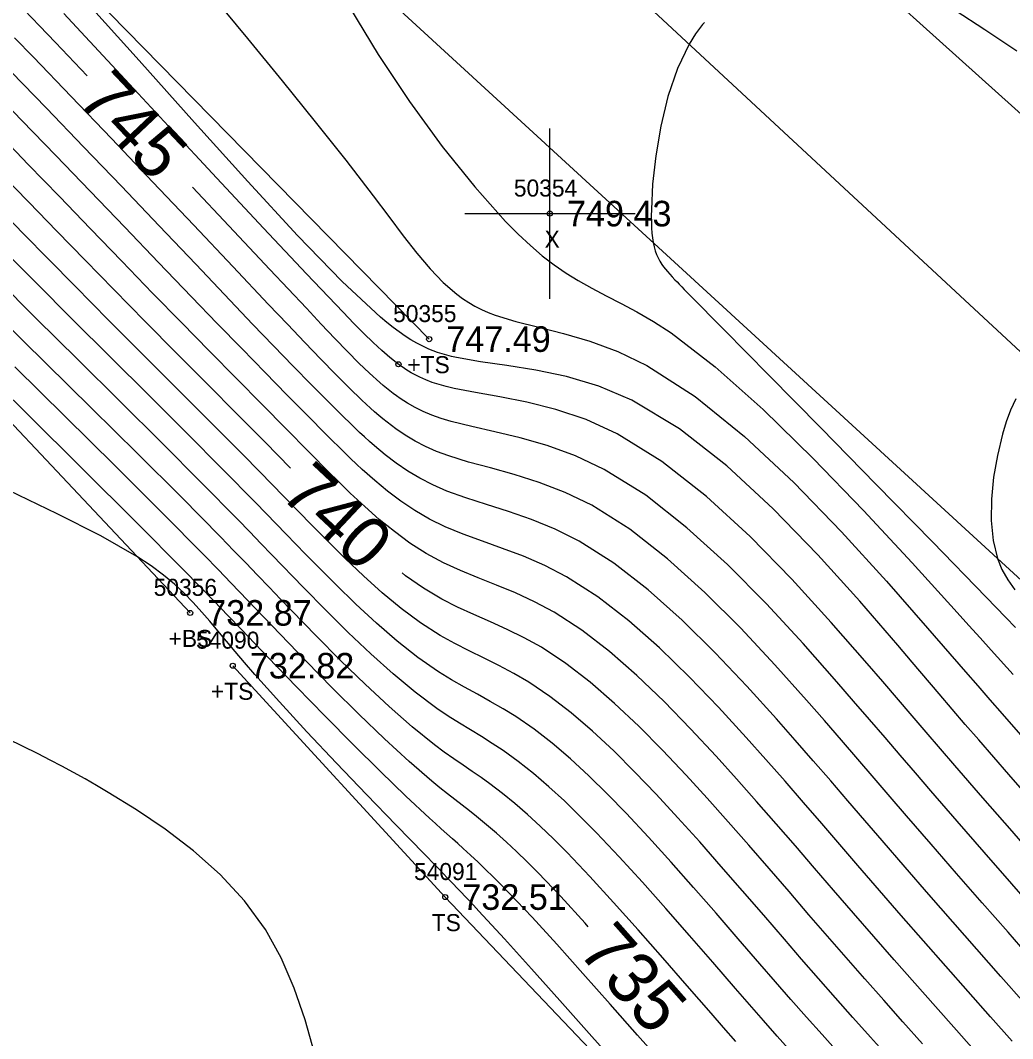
# Model space of a CAD drawing. Extents: x 1378535 to 1380697, y 997729 to 1000024.
# Drawn here: x 1379536.7 to 1379595, y 999000.3 to 999060.1 of the extents above; entities that cross this region are included whole.
import ezdxf

# ---------------------------------------------------------------- set-up
doc = ezdxf.new("R2010")
doc.units = 0
for name, color, linetype in [('RD_DTM_BkLn1', 7, 'Continuous'), ('RD_DTM_BkLn2', 7, 'Continuous'), ('RD_DTM_BkLn_txCode', 7, 'Continuous'), ('RD_DTM_Major1', 7, 'Continuous'), ('RD_DTM_Major1_Lbl', 7, 'Continuous'), ('RD_DTM_Minor1', 7, 'Continuous'), ('RD_EX_Misc', 7, 'Continuous'), ('RD_EX_Misc_txCode', 7, 'Continuous'), ('RD_EX_Road', 7, 'Continuous'), ('RD_EX_TX_Misc_ELEV', 7, 'Continuous'), ('RD_SMD_Locator', 7, 'Continuous')]:
    doc.layers.add(name, color=color, linetype=linetype)

msp = doc.modelspace()

# ---------------------------------------------------------------- linework, layer by layer
at = {"layer": 'RD_DTM_BkLn1'}
msp.add_lwpolyline([(1379644.889, 998995.516), (1379603.59, 999033.022), (1379560.539, 999073.024), (1379518.05, 999111.381), (1379475.069, 999150.602), (1379431.045, 999190.013), (1379385.062, 999231.968), (1379339.18, 999273.058), (1379294.588, 999314.047), (1379247.38, 999356.59), (1379201.7, 999398.205), (1379156.533, 999438.891)], dxfattribs=at)
at = {"layer": 'RD_DTM_BkLn2'}
for points in [[(1379560.71, 999041.369), (1379522.229, 999080.615), (1379488.974, 999108.847), (1379453.566, 999142.959)], [(1379546.679, 999025.297), (1379508.429, 999065.934), (1379476.253, 999096.185), (1379454.22, 999110.396), (1379428.749, 999089.976)], [(1379549.178, 999022.196), (1379561.654, 999008.614), (1379573.991, 998995.636), (1379587.739, 998979.101), (1379600.39, 998963.869), (1379618.836, 998956.235), (1379632.894, 998950.83), (1379660.439, 998956.621)]]:
    msp.add_lwpolyline(points, dxfattribs=at)
at = {"layer": 'RD_DTM_Major1'}
for points in [[(1379595.196, 999058.28), (1379593.322, 999059.53), (1379591.577, 999060.653), (1379590.026, 999061.63), (1379589.781, 999061.783), (1379589.544, 999061.931), (1379589.314, 999062.074), (1379589.09, 999062.212), (1379588.871, 999062.345), (1379588.658, 999062.473), (1379588.101, 999062.793), (1379587.565, 999063.071), (1379587.035, 999063.303), (1379586.498, 999063.483), (1379585.94, 999063.607), (1379585.346, 999063.67), (1379584.833, 999063.655)], [(1379552.566, 999033.796), (1379551.072, 999035.312), (1379549.431, 999036.967), (1379547.69, 999038.719), (1379545.882, 999040.541), (1379544.037, 999042.406), (1379542.188, 999044.285), (1379540.511, 999046.002), (1379538.852, 999047.709), (1379537.206, 999049.406), (1379535.566, 999051.093), (1379533.928, 999052.77), (1379532.286, 999054.438), (1379530.585, 999056.15), (1379528.884, 999057.849), (1379527.193, 999059.531), (1379525.522, 999061.194)], [(1379540.63, 999056.823), (1379538.777, 999058.772), (1379537.839, 999059.753), (1379536.943, 999060.69)], [(1379576.863, 999059.951), (1379576.761, 999059.84), (1379576.346, 999059.295), (1379575.964, 999058.691), (1379575.277, 999057.247), (1379574.727, 999055.611), (1379574.307, 999053.876), (1379574.009, 999052.132), (1379573.826, 999050.471), (1379573.75, 999048.983), (1379573.746, 999048.603), (1379573.751, 999048.246), (1379573.765, 999047.91), (1379573.787, 999047.598), (1379573.818, 999047.309), (1379573.858, 999047.043), (1379573.91, 999046.79), (1379573.974, 999046.558), (1379574.051, 999046.344), (1379574.142, 999046.142), (1379574.249, 999045.947), (1379574.372, 999045.755), (1379574.473, 999045.617), (1379574.583, 999045.475), (1379574.704, 999045.33), (1379574.836, 999045.179), (1379574.979, 999045.021), (1379575.134, 999044.854), (1379575.259, 999044.723), (1379575.392, 999044.585), (1379575.531, 999044.442), (1379575.678, 999044.291), (1379575.832, 999044.134), (1379575.994, 999043.97), (1379578.027, 999041.908), (1379580.656, 999039.245), (1379583.694, 999036.162), (1379586.956, 999032.842), (1379590.254, 999029.468), (1379593.403, 999026.219), (1379594.558, 999025.018), (1379595.121, 999024.43)], [(1379596.532, 999007.539), (1379594.914, 999009.391), (1379593.293, 999011.244), (1379591.697, 999013.073), (1379590.152, 999014.854), (1379589.248, 999015.904), (1379588.358, 999016.941), (1379587.468, 999017.979), (1379586.562, 999019.034), (1379585.625, 999020.118), (1379584.644, 999021.248), (1379582.657, 999023.494), (1379580.501, 999025.829), (1379578.216, 999028.137), (1379575.842, 999030.3), (1379573.419, 999032.201), (1379570.988, 999033.724), (1379569.293, 999034.522), (1379567.641, 999035.122), (1379566.058, 999035.575), (1379564.571, 999035.928), (1379563.207, 999036.231), (1379561.993, 999036.533), (1379561.404, 999036.713), (1379560.86, 999036.909), (1379560.354, 999037.123), (1379559.88, 999037.357), (1379559.43, 999037.612), (1379558.998, 999037.891), (1379558.799, 999038.03), (1379558.601, 999038.176), (1379558.404, 999038.327), (1379558.206, 999038.486), (1379558.007, 999038.652), (1379557.805, 999038.825), (1379557.214, 999039.361), (1379556.586, 999039.966), (1379555.91, 999040.646), (1379555.177, 999041.404), (1379554.377, 999042.246), (1379553.5, 999043.177), (1379551.362, 999045.449), (1379548.943, 999048.019), (1379546.812, 999050.282)], [(1379570.048, 999006.875), (1379569.857, 999007.088), (1379568.433, 999008.64), (1379567.101, 999010.037), (1379566.458, 999010.683), (1379565.842, 999011.281), (1379565.244, 999011.84), (1379564.658, 999012.365), (1379564.078, 999012.863), (1379563.496, 999013.341), (1379563.081, 999013.671), (1379561.791, 999014.677), (1379561.339, 999015.036), (1379560.873, 999015.417), (1379559.528, 999016.579), (1379558.089, 999017.902), (1379556.585, 999019.348), (1379555.042, 999020.879), (1379553.489, 999022.457), (1379551.953, 999024.045), (1379550.532, 999025.529), (1379549.077, 999027.049), (1379548.313, 999027.841), (1379547.513, 999028.665), (1379545.017, 999031.196), (1379542.26, 999033.948), (1379539.347, 999036.827), (1379536.383, 999039.738)], [(1379589.669, 999000.004), (1379588.519, 999001.289), (1379587.392, 999002.556), (1379586.283, 999003.813), (1379585.186, 999005.065), (1379584.095, 999006.318), (1379583.004, 999007.578), (1379581.837, 999008.932), (1379580.66, 999010.296), (1379579.47, 999011.667), (1379578.263, 999013.04), (1379577.035, 999014.411), (1379575.785, 999015.777), (1379574.411, 999017.231), (1379573.013, 999018.643), (1379571.596, 999019.984), (1379570.167, 999021.223), (1379568.732, 999022.331), (1379567.298, 999023.276), (1379566.29, 999023.836), (1379565.29, 999024.326), (1379564.302, 999024.772), (1379563.331, 999025.201), (1379562.38, 999025.638), (1379561.455, 999026.11), (1379560.37, 999026.757), (1379559.321, 999027.482), (1379559.119, 999027.64)]]:
    msp.add_lwpolyline(points, dxfattribs=at)
at = {"layer": 'RD_DTM_Minor1'}
for points in [[(1379598.415, 999011.597), (1379594.73, 999015.806), (1379592.965, 999017.837), (1379592.181, 999018.747), (1379591.41, 999019.648), (1379590.639, 999020.552), (1379589.053, 999022.413), (1379588.215, 999023.395), (1379585.981, 999025.98), (1379583.528, 999028.703), (1379580.91, 999031.405), (1379578.181, 999033.927), (1379575.394, 999036.109), (1379572.604, 999037.791), (1379570.665, 999038.611), (1379568.779, 999039.175), (1379566.972, 999039.553), (1379565.274, 999039.816), (1379563.712, 999040.035), (1379562.313, 999040.282), (1379562.024, 999040.348), (1379561.743, 999040.421), (1379561.471, 999040.499), (1379561.204, 999040.586), (1379560.943, 999040.68), (1379560.686, 999040.783), (1379560.567, 999040.835), (1379560.448, 999040.889), (1379560.329, 999040.946), (1379560.211, 999041.005), (1379560.093, 999041.066), (1379559.975, 999041.13), (1379559.639, 999041.326), (1379559.299, 999041.545), (1379558.953, 999041.787), (1379558.598, 999042.053), (1379558.23, 999042.346), (1379557.848, 999042.666), (1379555.602, 999044.755), (1379552.975, 999047.456), (1379550.056, 999050.618), (1379546.93, 999054.089), (1379543.687, 999057.72), (1379540.413, 999061.36)], [(1379547.953, 999061.567), (1379550.052, 999059.015), (1379552.087, 999056.522), (1379554.018, 999054.127), (1379555.807, 999051.868), (1379557.415, 999049.784), (1379558.333, 999048.563), (1379559.183, 999047.437), (1379559.986, 999046.41), (1379560.763, 999045.492), (1379561.535, 999044.687), (1379562.323, 999044.004), (1379562.67, 999043.751), (1379563.027, 999043.519), (1379563.394, 999043.307), (1379563.776, 999043.114), (1379564.174, 999042.938), (1379564.591, 999042.776), (1379565.798, 999042.403), (1379567.137, 999042.063), (1379568.592, 999041.696), (1379570.147, 999041.241), (1379571.785, 999040.639), (1379573.489, 999039.828), (1379576.329, 999038.004), (1379579.226, 999035.654), (1379582.11, 999032.949), (1379584.908, 999030.057), (1379587.551, 999027.15), (1379589.966, 999024.398), (1379592.194, 999021.83), (1379592.907, 999021.009), (1379593.618, 999020.191), (1379594.338, 999019.367), (1379596.25, 999017.191)], [(1379556.031, 999060.851), (1379557.715, 999058.071), (1379559.558, 999055.311), (1379561.474, 999052.684), (1379563.38, 999050.3), (1379565.188, 999048.273), (1379565.931, 999047.524), (1379566.648, 999046.855), (1379567.349, 999046.257), (1379568.044, 999045.722), (1379568.742, 999045.239), (1379569.453, 999044.8), (1379570.261, 999044.352), (1379571.103, 999043.917), (1379571.982, 999043.467), (1379572.905, 999042.974), (1379573.879, 999042.408), (1379574.908, 999041.742), (1379577.504, 999039.747), (1379580.322, 999037.231), (1379583.258, 999034.362), (1379586.205, 999031.308), (1379589.057, 999028.237), (1379591.71, 999025.319), (1379592.392, 999024.563), (1379593.056, 999023.826), (1379593.708, 999023.102), (1379594.993, 999021.673)], [(1379596.66, 999010.496), (1379594.925, 999012.479), (1379593.215, 999014.435), (1379591.566, 999016.334), (1379590.72, 999017.317), (1379589.888, 999018.288), (1379589.056, 999019.26), (1379587.337, 999021.266), (1379586.423, 999022.326), (1379584.314, 999024.738), (1379582.006, 999027.268), (1379579.548, 999029.778), (1379576.986, 999032.131), (1379574.369, 999034.189), (1379571.744, 999035.814), (1379569.916, 999036.643), (1379568.139, 999037.244), (1379566.444, 999037.671), (1379564.863, 999037.981), (1379563.427, 999038.229), (1379562.167, 999038.471), (1379561.713, 999038.579), (1379561.29, 999038.697), (1379560.891, 999038.827), (1379560.515, 999038.971), (1379560.155, 999039.131), (1379559.808, 999039.308), (1379559.649, 999039.399), (1379559.49, 999039.494), (1379559.333, 999039.594), (1379559.175, 999039.699), (1379559.018, 999039.81), (1379558.859, 999039.926), (1379558.402, 999040.289), (1379557.924, 999040.703), (1379557.419, 999041.172), (1379556.877, 999041.701), (1379556.29, 999042.292), (1379555.651, 999042.95), (1379553.502, 999045.203), (1379550.985, 999047.879), (1379548.239, 999050.822), (1379545.401, 999053.875), (1379542.61, 999056.882), (1379540.002, 999059.687), (1379539.267, 999060.475)], [(1379596.189, 999004.84), (1379594.69, 999006.552), (1379593.177, 999008.281), (1379591.666, 999010.008), (1379590.178, 999011.715), (1379588.731, 999013.386), (1379587.771, 999014.5), (1379586.825, 999015.602), (1379585.876, 999016.706), (1379584.911, 999017.825), (1379583.913, 999018.973), (1379582.867, 999020.164), (1379581.001, 999022.25), (1379578.996, 999024.394), (1379576.885, 999026.5), (1379574.702, 999028.471), (1379572.479, 999030.208), (1379570.251, 999031.616), (1379568.694, 999032.371), (1379567.173, 999032.958), (1379565.707, 999033.422), (1379564.317, 999033.806), (1379563.026, 999034.155), (1379561.855, 999034.514), (1379561.145, 999034.78), (1379560.489, 999035.07), (1379559.879, 999035.386), (1379559.305, 999035.728), (1379558.76, 999036.097), (1379558.233, 999036.493), (1379557.99, 999036.689), (1379557.747, 999036.891), (1379557.504, 999037.101), (1379557.26, 999037.319), (1379557.012, 999037.546), (1379556.759, 999037.781), (1379556.012, 999038.502), (1379555.208, 999039.304), (1379554.342, 999040.192), (1379553.405, 999041.169), (1379552.388, 999042.238), (1379551.285, 999043.405), (1379549.185, 999045.626), (1379546.89, 999048.051), (1379544.486, 999050.585), (1379542.059, 999053.136), (1379539.695, 999055.609), (1379537.48, 999057.911), (1379536.373, 999059.054)], [(1379595.655, 999002.377), (1379594.263, 999003.96), (1379592.856, 999005.56), (1379591.446, 999007.167), (1379590.044, 999008.771), (1379588.659, 999010.361), (1379587.304, 999011.926), (1379586.292, 999013.102), (1379585.289, 999014.269), (1379584.281, 999015.438), (1379583.255, 999016.622), (1379582.197, 999017.83), (1379581.093, 999019.076), (1379579.346, 999021.004), (1379577.491, 999022.961), (1379575.555, 999024.869), (1379573.563, 999026.649), (1379571.541, 999028.223), (1379569.516, 999029.513), (1379568.099, 999030.22), (1379566.71, 999030.787), (1379565.363, 999031.253), (1379564.075, 999031.659), (1379562.862, 999032.044), (1379561.74, 999032.447), (1379560.921, 999032.805), (1379560.16, 999033.198), (1379559.446, 999033.626), (1379558.771, 999034.087), (1379558.125, 999034.58), (1379557.497, 999035.103), (1379557.206, 999035.359), (1379556.915, 999035.623), (1379556.622, 999035.895), (1379556.325, 999036.175), (1379556.024, 999036.465), (1379555.715, 999036.766), (1379554.793, 999037.68), (1379553.797, 999038.686), (1379552.726, 999039.784), (1379551.577, 999040.974), (1379550.347, 999042.256), (1379549.034, 999043.631), (1379547.003, 999045.76), (1379544.853, 999048.017), (1379542.638, 999050.338), (1379540.415, 999052.66), (1379538.242, 999054.919), (1379536.175, 999057.052)], [(1379594.924, 999000.162), (1379593.658, 999001.589), (1379592.343, 999003.074), (1379591.029, 999004.562), (1379589.721, 999006.05), (1379588.424, 999007.534), (1379587.14, 999009.009), (1379585.874, 999010.472), (1379584.809, 999011.708), (1379583.749, 999012.94), (1379582.682, 999014.176), (1379581.596, 999015.423), (1379580.479, 999016.69), (1379579.321, 999017.983), (1379577.694, 999019.754), (1379575.99, 999021.527), (1379574.228, 999023.24), (1379572.426, 999024.834), (1379570.604, 999026.247), (1379568.779, 999027.419), (1379567.502, 999028.078), (1379566.244, 999028.621), (1379565.017, 999029.085), (1379563.833, 999029.504), (1379562.704, 999029.915), (1379561.64, 999030.352), (1379560.722, 999030.804), (1379559.86, 999031.305), (1379559.045, 999031.851), (1379558.266, 999032.437), (1379557.515, 999033.061), (1379556.78, 999033.716), (1379556.438, 999034.035), (1379556.095, 999034.362), (1379555.749, 999034.697), (1379555.398, 999035.042), (1379555.039, 999035.398), (1379554.67, 999035.766), (1379553.561, 999036.881), (1379552.36, 999038.097), (1379551.073, 999039.409), (1379549.707, 999040.81), (1379548.267, 999042.294), (1379546.76, 999043.854), (1379544.828, 999045.863), (1379542.835, 999047.941), (1379540.812, 999050.05), (1379538.79, 999052.152), (1379536.8, 999054.209), (1379534.874, 999056.185)], [(1379592.999, 998999.304), (1379591.663, 999000.798), (1379590.428, 999002.183), (1379589.208, 999003.561), (1379588.001, 999004.932), (1379586.805, 999006.299), (1379585.619, 999007.662), (1379584.44, 999009.023), (1379583.325, 999010.318), (1379582.207, 999011.616), (1379581.078, 999012.919), (1379579.932, 999014.229), (1379578.758, 999015.55), (1379577.551, 999016.884), (1379576.048, 999018.497), (1379574.496, 999020.088), (1379572.908, 999021.612), (1379571.294, 999023.025), (1379569.667, 999024.283), (1379568.04, 999025.34), (1379566.899, 999025.948), (1379565.771, 999026.466), (1379564.664, 999026.923), (1379563.586, 999027.35), (1379562.544, 999027.778), (1379561.546, 999028.237), (1379560.54, 999028.786), (1379559.582, 999029.398), (1379558.666, 999030.066), (1379557.782, 999030.782), (1379556.922, 999031.539), (1379556.076, 999032.33), (1379555.681, 999032.713), (1379555.285, 999033.103), (1379554.884, 999033.502), (1379554.475, 999033.913), (1379554.057, 999034.335), (1379553.625, 999034.772), (1379552.319, 999036.094), (1379550.902, 999037.527), (1379549.392, 999039.057), (1379547.805, 999040.668), (1379546.161, 999042.345), (1379544.476, 999044.073), (1379542.664, 999045.943), (1379540.836, 999047.836), (1379539.003, 999049.736), (1379537.176, 999051.626), (1379535.364, 999053.49)], [(1379587.675, 998999.21), (1379586.613, 999000.39), (1379585.581, 999001.548), (1379584.568, 999002.693), (1379583.567, 999003.833), (1379582.569, 999004.978), (1379581.565, 999006.136), (1379580.346, 999007.548), (1379579.108, 999008.98), (1379577.855, 999010.419), (1379576.588, 999011.854), (1379575.31, 999013.272), (1379574.024, 999014.661), (1379572.785, 999015.953), (1379571.541, 999017.19), (1379570.295, 999018.354), (1379569.047, 999019.428), (1379567.799, 999020.393), (1379566.552, 999021.232), (1379565.673, 999021.743), (1379564.798, 999022.204), (1379563.927, 999022.637), (1379563.063, 999023.061), (1379562.208, 999023.5), (1379561.362, 999023.975), (1379560.207, 999024.72), (1379559.072, 999025.56), (1379557.956, 999026.479), (1379556.856, 999027.463), (1379555.768, 999028.495), (1379554.692, 999029.561), (1379554.188, 999030.07), (1379553.682, 999030.587), (1379553.168, 999031.114), (1379552.102, 999032.21), (1379551.541, 999032.785), (1379549.823, 999034.529), (1379547.953, 999036.411), (1379545.978, 999038.389), (1379543.945, 999040.422), (1379541.904, 999042.469), (1379539.901, 999044.489), (1379538.373, 999046.042), (1379536.883, 999047.564), (1379535.416, 999049.066)], [(1379584.71, 998999.489), (1379583.772, 999000.538), (1379582.854, 999001.573), (1379581.947, 999002.604), (1379581.04, 999003.641), (1379580.124, 999004.695), (1379578.851, 999006.167), (1379577.551, 999007.668), (1379576.233, 999009.176), (1379574.908, 999010.67), (1379573.585, 999012.129), (1379572.272, 999013.531), (1379571.173, 999014.661), (1379570.085, 999015.728), (1379569.007, 999016.724), (1379567.936, 999017.641), (1379566.868, 999018.472), (1379565.801, 999019.21), (1379565.047, 999019.674), (1379564.293, 999020.105), (1379563.537, 999020.519), (1379562.781, 999020.935), (1379562.023, 999021.367), (1379561.263, 999021.835), (1379560.048, 999022.68), (1379558.831, 999023.637), (1379557.616, 999024.685), (1379556.405, 999025.804), (1379555.201, 999026.975), (1379554.007, 999028.177), (1379553.449, 999028.749), (1379552.887, 999029.327), (1379552.318, 999029.916), (1379551.735, 999030.519), (1379551.133, 999031.14), (1379550.506, 999031.784), (1379548.579, 999033.74), (1379546.477, 999035.849), (1379544.264, 999038.055), (1379542.006, 999040.301), (1379539.77, 999042.529), (1379537.619, 999044.683), (1379536.249, 999046.064)], [(1379581.965, 998999.527), (1379581.141, 999000.453), (1379580.326, 999001.375), (1379579.511, 999002.304), (1379578.685, 999003.251), (1379577.353, 999004.786), (1379575.987, 999006.357), (1379574.605, 999007.934), (1379573.224, 999009.485), (1379571.86, 999010.98), (1379570.531, 999012.386), (1379569.578, 999013.353), (1379568.648, 999014.255), (1379567.735, 999015.092), (1379566.834, 999015.864), (1379565.938, 999016.572), (1379565.044, 999017.216), (1379564.41, 999017.634), (1379563.772, 999018.033), (1379563.129, 999018.425), (1379562.479, 999018.824), (1379561.821, 999019.243), (1379561.154, 999019.693), (1379559.888, 999020.639), (1379558.593, 999021.714), (1379557.28, 999022.893), (1379555.958, 999024.149), (1379554.636, 999025.459), (1379553.324, 999026.795), (1379552.712, 999027.427), (1379552.097, 999028.065), (1379551.473, 999028.713), (1379550.833, 999029.377), (1379550.172, 999030.061), (1379549.481, 999030.771), (1379547.349, 999032.935), (1379545.015, 999035.271), (1379542.564, 999037.705), (1379540.079, 999040.165), (1379537.644, 999042.576), (1379535.342, 999044.866)], [(1379578.708, 999000.143), (1379577.987, 999000.961), (1379577.256, 999001.793), (1379575.856, 999003.398), (1379574.42, 999005.044), (1379572.972, 999006.69), (1379571.537, 999008.295), (1379570.141, 999009.82), (1379568.806, 999011.222), (1379568.006, 999012.027), (1379567.233, 999012.772), (1379566.481, 999013.462), (1379565.742, 999014.103), (1379565.01, 999014.7), (1379564.277, 999015.257), (1379563.757, 999015.63), (1379563.23, 999015.995), (1379562.696, 999016.361), (1379562.152, 999016.736), (1379561.596, 999017.13), (1379561.027, 999017.552), (1379559.719, 999018.602), (1379558.352, 999019.798), (1379556.942, 999021.109), (1379555.509, 999022.503), (1379554.069, 999023.95), (1379552.64, 999025.417), (1379551.976, 999026.107), (1379551.309, 999026.801), (1379550.634, 999027.505), (1379549.941, 999028.226), (1379549.223, 999028.969), (1379548.472, 999029.741), (1379546.141, 999032.104), (1379543.581, 999034.661), (1379540.893, 999037.324), (1379535.531, 999042.607)], [(1379574.553, 998998.696), (1379572.946, 999000.503), (1379571.331, 999002.329), (1379569.738, 999004.126), (1379568.199, 999005.843), (1379566.746, 999007.434), (1379565.411, 999008.847), (1379564.931, 999009.338), (1379564.47, 999009.8), (1379564.02, 999010.239), (1379563.579, 999010.661), (1379563.141, 999011.07), (1379562.702, 999011.472), (1379562.388, 999011.754), (1379562.07, 999012.039), (1379561.746, 999012.328), (1379561.414, 999012.624), (1379561.073, 999012.931), (1379560.722, 999013.25), (1379559.345, 999014.538), (1379557.842, 999015.992), (1379556.247, 999017.574), (1379554.594, 999019.244), (1379552.915, 999020.963), (1379551.243, 999022.693), (1379550.467, 999023.502), (1379549.688, 999024.314), (1379548.896, 999025.139), (1379548.079, 999025.986), (1379547.227, 999026.864), (1379546.327, 999027.785), (1379543.496, 999030.639), (1379540.366, 999033.753), (1379537.105, 999036.976), (1379533.881, 999040.161)], [(1379595.145, 999037.867), (1379594.836, 999037.207), (1379594.578, 999036.511), (1379594.358, 999035.78), (1379594.061, 999034.543), (1379593.844, 999033.261), (1379593.721, 999031.976), (1379593.707, 999030.727), (1379593.817, 999029.553), (1379594.066, 999028.495), (1379594.33, 999027.836), (1379594.67, 999027.229), (1379595.085, 999026.653)], [(1379571.888, 998998.614), (1379570.104, 999000.609), (1379568.376, 999002.548), (1379566.716, 999004.407), (1379565.131, 999006.163), (1379563.631, 999007.795), (1379563.318, 999008.13), (1379563.008, 999008.459), (1379562.393, 999009.107), (1379562.084, 999009.429), (1379561.773, 999009.752), (1379561.552, 999009.981), (1379561.328, 999010.212), (1379560.873, 999010.68), (1379560.641, 999010.918), (1379560.406, 999011.16), (1379558.768, 999012.842), (1379557.031, 999014.637), (1379555.263, 999016.482), (1379553.534, 999018.313), (1379551.914, 999020.069), (1379550.471, 999021.686), (1379549.871, 999022.383), (1379549.316, 999023.04), (1379548.305, 999024.249), (1379547.83, 999024.81), (1379547.363, 999025.348), (1379546.858, 999025.907), (1379546.329, 999026.451), (1379545.756, 999026.987), (1379545.117, 999027.521), (1379544.39, 999028.062), (1379543.554, 999028.617), (1379541.431, 999029.827), (1379538.879, 999031.117), (1379536.031, 999032.478)], [(1379553.984, 998999.458), (1379553.42, 999001.399), (1379552.78, 999003.266), (1379552.022, 999005.041), (1379551.101, 999006.705), (1379549.866, 999008.394), (1379548.437, 999009.933), (1379546.868, 999011.331), (1379545.214, 999012.596), (1379543.529, 999013.737), (1379541.867, 999014.763), (1379541.183, 999015.165), (1379540.507, 999015.551), (1379539.832, 999015.926), (1379539.152, 999016.294), (1379538.46, 999016.657), (1379537.752, 999017.021), (1379535.964, 999017.909)]]:
    msp.add_lwpolyline(points, dxfattribs=at)
at = {"layer": 'RD_EX_Misc'}
for p, q in [((1379567.797, 999043.737), (1379567.797, 999053.737)), ((1379562.797, 999048.737), (1379572.797, 999048.737))]:
    msp.add_line(p, q, dxfattribs=at)
at = {"layer": 'RD_EX_Road'}
for points in [[(1379652.216, 999003.544), (1379610.671, 999040.913), (1379567.405, 999079.792), (1379524.774, 999119.811), (1379481.793, 999158.312), (1379438.693, 999197.69), (1379392.81, 999238.626), (1379346.749, 999280.784), (1379301.799, 999321.656), (1379254.546, 999364.519), (1379209.475, 999405.54), (1379163.997, 999446.485)], [(1379637.067, 998987.215), (1379597.137, 999025.676), (1379553.307, 999065.907), (1379510.702, 999104.297), (1379468.488, 999142.894), (1379424.884, 999182.89), (1379377.902, 999224.837), (1379333.605, 999264.984), (1379287.277, 999307.211), (1379240.784, 999348.984), (1379194.921, 999391.17), (1379151.382, 999431.093)]]:
    msp.add_lwpolyline(points, dxfattribs=at)
at = {"layer": 'RD_SMD_Locator'}
for centre in [(1379567.797, 999048.737), (1379560.71, 999041.369), (1379558.905, 999039.89), (1379546.679, 999025.297), (1379549.178, 999022.196), (1379561.654, 999008.614)]:
    msp.add_circle(centre, 0.15, dxfattribs=at)

# ---------------------------------------------------------------- texts
at = {"layer": 'RD_DTM_BkLn_txCode'}
for s, p in [('50355', (1379558.592, 999042.369)), ('+TS', (1379559.427, 999039.369)), ('50356', (1379544.537, 999026.297)), ('+BS', (1379545.411, 999023.297)), ('54090', (1379547.021, 999023.196)), ('+TS', (1379547.895, 999020.196)), ('54091', (1379559.819, 999009.614)), ('TS', (1379560.859, 999006.614))]:
    msp.add_text(s, height=1, dxfattribs=at).set_placement(p)
at = {"layer": 'RD_DTM_Major1_Lbl'}
for s, rotation, p in [('745', 313.38533, (1379539.957, 999055.358)), ('740', 316.78788, (1379551.868, 999032.178)), ('735', 311.45734, (1379569.363, 999005.402))]:
    msp.add_text(s, height=3, rotation=rotation, dxfattribs=at).set_placement(p)
at = {"layer": 'RD_EX_Misc_txCode'}
for s, p in [('50354', (1379565.679, 999049.737)), ('X', (1379567.482, 999046.737))]:
    msp.add_text(s, height=1, dxfattribs=at).set_placement(p)
at = {"layer": 'RD_EX_TX_Misc_ELEV'}
for s, p in [('749.43', (1379568.797, 999047.987)), ('747.49', (1379561.71, 999040.619)), ('732.87', (1379547.679, 999024.547)), ('732.82', (1379550.178, 999021.446)), ('732.51', (1379562.654, 999007.864))]:
    msp.add_text(s, height=1.5, dxfattribs=at).set_placement(p)

doc.saveas('drawing.dxf')
